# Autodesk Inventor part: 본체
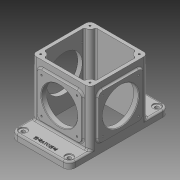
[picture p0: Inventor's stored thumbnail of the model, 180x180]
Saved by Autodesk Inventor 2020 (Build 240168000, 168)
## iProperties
Created: 2018-09
Part Number: 본체
Material: 알루미늄 6061
Document SubType Name: Modeling
Designer: mduedu
Density: 2.71 g/cm^3
Mass: 972.977 g
Surface Area: 957.184 cm^2
Volume: 359.032 cm^3
Appearance: 기본값
Author: mduedu
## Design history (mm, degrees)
sketch "스케치1"
  geometry: L1 (90, 52.5)-(-90, 52.5); L2 (-90, 52.5)-(-90, -52.5); L3 (-90, -52.5)-(90, -52.5); L4 (90, -52.5)-(90, 52.5); L5 (90, 52.5)-(-90, -52.5); L6 (-90, 52.5)-(90, -52.5); 1 further point
  constraints: 12 end point, 2 midpoint, 2 parallel, 1 horizontal, 1 perpendicular
  dimensions: "d0" = 180 distance of L3.end L2.end; "d1" = 105 distance of L2.end L1.end
extrude "돌출1" new body sketch "스케치1" distance "d2" = 12; taper "d3" = 0 deg
sketch "스케치2"
  geometry: L1 (-52.5, -52.5)-(52.5, -52.5); L2 (52.5, -52.5)-(52.5, 52.5); L3 (52.5, 52.5)-(-52.5, 52.5); L4 (-52.5, 52.5)-(-52.5, -52.5); L5 (-52.5, -52.5)-(52.5, 52.5); L6 (52.5, -52.5)-(-52.5, 52.5); 1 further point
  constraints: 12 end point, 2 midpoint, 2 parallel, 1 horizontal, 1 perpendicular
  dimensions: "d4" = 105 distance of L3.end L2.end; "d5" = 105 distance of L2.end L1.end
extrude "돌출2" join sketch "스케치2" distance "d6" = 100; taper "d7" = 0 deg
sketch "스케치14"
  geometry: L1 (-52.5, 52.5)-(52.5, 52.5) reference; L2 (52.5, 52.5)-(52.5, -52.5) reference; L3 (52.5, -52.5)-(-52.5, -52.5) reference; L4 (-52.5, -52.5)-(-52.5, 52.5) reference; L5 (46.5, 46.5)-(-46.5, 46.5); L6 (-46.5, 46.5)-(-46.5, -46.5); L7 (-46.5, -46.5)-(46.5, -46.5); L8 (46.5, -46.5)-(46.5, 46.5); 1 further point
  constraints: 8 end point, 3 other
  dimensions: "d85" = 6 distance between parallel lines of L5 L1
extrude "돌출10" cut sketch "스케치14" extent not by distance; stored distance "d86" = 10; taper "d87" = 0 deg
fillet "모깎기1" dims "d12" = 8
sketch "스케치15"
  geometry: A1 r 8 centre (-44.5, 44.5) between (-44.5, 52.5) and (-52.5, 44.5) reference; A2 r 8 centre (44.5, 44.5) between (52.5, 44.5) and (44.5, 52.5) reference; A3 r 8 centre (44.5, -44.5) between (44.5, -52.5) and (52.5, -44.5) reference; A4 r 8 centre (-44.5, -44.5) between (-52.5, -44.5) and (-44.5, -52.5) reference; 5 further points
  constraints: 4 coincident, 4 vertical alignment, 8 other
extrude "돌출11" join sketch "스케치15" stored distance "d88" = 10; taper "d89" = 0 deg
fillet "모깎기15" dims "d90" = 3
sketch "스케치6"
  geometry: L1 (50, 19)-(130, 19); L2 (130, 19)-(130, 99); L3 (130, 99)-(50, 99); L4 (50, 99)-(50, 19); L5 (50, 19)-(130, 99); L6 (130, 19)-(50, 99); L7 (0, 0)-(180, 0) reference; 4 further points
  constraints: 12 end point, 4 midpoint, 2 parallel, 1 horizontal, 1 perpendicular, 1 vertical alignment
  dimensions: "d25" = 80 distance of L3.end L2.end; "d26" = 80 distance of L2.end L1.end; "d27" = 59 distance of point (90, 0) point (90, 59)
extrude "돌출6" join sketch "스케치6" distance "d28" = 3; taper "d29" = 0 deg
fillet "모깎기7" dims "d30" = 8
sketch "스케치7"
  geometry: C1 r 32.5 at (90, 59); 1 further point
  constraints: 1 centre point, 1 vertical alignment
  dimensions: "d32" = 65 diameter of C1; "d33" = 59 distance of C1.centre point (90, 0)
extrude "돌출7" cut sketch "스케치7" stored distance "d34" = 3; taper "d35" = 0 deg
fillet "모깎기9" dims "d36" = 3
sketch "스케치8"
  geometry: L1 (4.5, 7)-(84.5, 7); L2 (84.5, 7)-(84.5, 87); L3 (84.5, 87)-(4.5, 87); L4 (4.5, 87)-(4.5, 7); L5 (4.5, 7)-(84.5, 87); L6 (84.5, 7)-(4.5, 87); L7 (-8, -12)-(97, -12) reference; C1 r 32.5 at (44.5, 47); 4 further points
  constraints: 12 end point, 4 midpoint, 2 parallel, 1 centre point, 1 coincident, 1 horizontal, 1 perpendicular, 1 vertical alignment
  dimensions: "d37" = 80 distance of L3.end L2.end; "d38" = 80 distance of L2.end L1.end; "d39" = 59 distance from line of point (44.5, 47) L7; "d40" = 65 diameter of C1
extrude "돌출8" join sketch "스케치8" distance "d41" = 3; taper "d42" = 0 deg
fillet "모깎기10" dims "d43" = 8
extrude "돌출9" cut sketch "스케치8" stored distance "d44" = 3; taper "d45" = 0 deg
fillet "모깎기11" dims "d46" = 3
sketch "스케치9"
  geometry: L1 (50, 91)-(50, 27) reference; L2 (58, 19)-(122, 19) reference; L3 (130, 27)-(130, 91) reference; L4 (122, 99)-(58, 99) reference; C1 r 32.5 at (90, 59) reference; A1 r 8 centre (58, 91) between (58, 99) and (50, 91) reference; A2 r 8 centre (58, 27) between (50, 27) and (58, 19) reference; A3 r 8 centre (122, 27) between (122, 19) and (130, 27) reference; A4 r 8 centre (122, 91) between (130, 91) and (122, 99) reference; 5 further points
  constraints: 4 coincident
hole "구멍1" sketch "스케치9" at (58, 91), (122, 91), (122, 27), (58, 27) diameter "d47" = 3.242; stored, may be unused: countersink angle "d51" = 90 deg, drill point angle "d53" = 118 deg; dims "d48" = 6, "d49" = 4, "d50" = 2, "d52" = 9
sketch "스케치10"
  geometry: L1 (12.5, 7)-(76.5, 7) reference; L2 (84.5, 15)-(84.5, 79) reference; L3 (76.5, 87)-(12.5, 87) reference; L4 (4.5, 79)-(4.5, 15) reference; C1 r 32.5 at (44.5, 47) reference; A1 r 8 centre (12.5, 15) between (4.5, 15) and (12.5, 7) reference; A2 r 8 centre (76.5, 15) between (76.5, 7) and (84.5, 15) reference; A3 r 8 centre (76.5, 79) between (84.5, 79) and (76.5, 87) reference; A4 r 8 centre (12.5, 79) between (12.5, 87) and (4.5, 79) reference; 5 further points
  constraints: 4 coincident
hole "구멍2" sketch "스케치10" at (12.5, 79), (76.5, 79), (76.5, 15), (12.5, 15) diameter "d54" = 3.242; stored, may be unused: countersink angle "d58" = 90 deg, drill point angle "d60" = 118 deg; dims "d55" = 6, "d56" = 4, "d57" = 2, "d59" = 9
fillet "모깎기12" dims "d68" = 11
sketch "스케치16"
  geometry: A1 r 11 centre (-79, 41.5) between (-79, 52.5) and (-90, 41.5) reference; A2 r 11 centre (-79, -41.5) between (-90, -41.5) and (-79, -52.5) reference; A3 r 11 centre (79, 41.5) between (90, 41.5) and (79, 52.5) reference; A4 r 11 centre (79, -41.5) between (79, -52.5) and (90, -41.5) reference; 5 further points
  constraints: 4 coincident
hole "구멍5" sketch "스케치16" at (-79, 41.5), (79, 41.5), (79, -41.5), (-79, -41.5) diameter "d91" = 6.6; stored, may be unused: countersink angle "d95" = 90 deg, drill point angle "d97" = 118 deg; dims "d92" = 6, "d93" = 14, "d94" = 2, "d96" = 8
fillet "모깎기13" dims "d77" = 3
fillet "모깎기14" dims "d78" = 3
chamfer "모따기1" distance "d79" = 1; stored, may be unused: second distance "d80" = 2, angle "d81" = 45 deg
sketch "스케치17"
  geometry: A1 r 8 centre (-44.5, 44.5) between (-44.5, 52.5) and (-52.5, 44.5) reference; A2 r 8 centre (-44.5, -44.5) between (-52.5, -44.5) and (-44.5, -52.5) reference; A3 r 8 centre (44.5, -44.5) between (44.5, -52.5) and (52.5, -44.5) reference; A4 r 8 centre (44.5, 44.5) between (52.5, 44.5) and (44.5, 52.5) reference; 5 further points
  constraints: 4 coincident
hole "구멍6" sketch "스케치17" at (-44.5, 44.5), (44.5, 44.5), (44.5, -44.5), (-44.5, -44.5) diameter "d98" = 3.242; stored, may be unused: countersink angle "d102" = 90 deg, drill point angle "d104" = 118 deg; dims "d99" = 8, "d100" = 15, "d101" = 2, "d103" = 10
sketch "스케치13"
  geometry: L1 (90, -41.5)-(90, 41.5) reference; 2 further points
  constraints: 1 horizontal alignment, 1 other
  dimensions: "d82" = 10 distance from line of point (80, 0) L1
feature "엠보싱1" sketch "스케치13" dims "d0" = 180, "d1" = 105, "d25" = 80, "d26" = 80, "d27" = 59, "d83" = 0.5, "d84" = 0
node "솔리드1"
mirror "대칭1"
mirror "대칭2"
node "투영된 루프2"
node "투영된 루프3"
node "투영된 루프6"
